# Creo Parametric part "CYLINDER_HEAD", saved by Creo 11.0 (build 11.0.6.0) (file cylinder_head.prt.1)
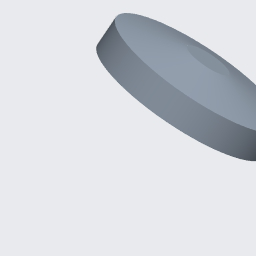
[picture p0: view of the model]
Materials in the file: 10038_S235JR

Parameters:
  MATERIAL = "10038_S235JR"
  PTC_MATERIAL_NAME = "10038_S235JR"
  PTC_MASTER_MATERIAL = "10038_S235JR"
  SELECT_EN_NAME = "S235JR"
  SELECT_DIN_NAME = "RSt37-2"
  SELECT_MATERIAL_NUMBER = "1.0038"
  SELECT_ASTM_NAME = "A 283 M Grade 2"
  MATERIAL_GROUP = "ME_ST_Baustahl"
  STANDARD_EN_DELIVERYSPEC = "DIN EN 10025-2"
  STANDARD_DIN_DELIVERYSPEC = "DIN EN 10025-2"

Other parameters: GEWICHT

Created from: STARTTEIL.PRT

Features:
  1. datum plane "RIGHT"
  2. datum plane "TOP"
  3. datum plane "FRONT"
  4. coordinate system
  5. datum axis
  6. datum axis
  7. datum axis
  8. revolve "Revolve 1"

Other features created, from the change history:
  extrusion "Extrude 1"

Other named items: A_Y, A_X, A_Z, CS0

Surfaces: 2 plane, 2 cylinder, 2 cone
